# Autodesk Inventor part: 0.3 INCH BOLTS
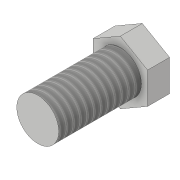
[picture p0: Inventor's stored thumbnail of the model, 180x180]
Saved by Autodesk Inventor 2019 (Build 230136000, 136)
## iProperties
Created: 2019-10
Part Number: 0.3 INCH BOLTS
Material: Generic
Document SubType Name: Modeling
Designer: hp
Density: 1 g/cm^3
Appearance: Default
Author: hp
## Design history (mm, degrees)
sketch "Sketch1"
  geometry: L1 (-7.387, 9.259)-(-2.439, 6.403); L2 (-2.439, 6.403)-(-2.439, 0.689); L3 (-2.439, 0.689)-(-7.387, -2.167); L4 (-7.387, -2.167)-(-12.335, 0.689); L5 (-12.335, 0.689)-(-12.335, 6.403); L6 (-12.335, 6.403)-(-7.387, 9.259); 2 further points
  constraints: 12 end point, 13 other
extrude "Extrusion1" new body sketch "Sketch1" distance "d1" = 4; taper "d2" = 0 deg
sketch "Sketch2"
  geometry: C1 r 3.81 at (-7.368, 3.684); 1 further point
  constraints: 1 centre point
  dimensions: "d3" = 7.62 diameter of C1
extrude "Extrusion2" join sketch "Sketch2" distance "d4" = 15; taper "d5" = 0 deg
thread "Thread1" dims "d6" = 10, "d7" = 0
body "Solid1"
